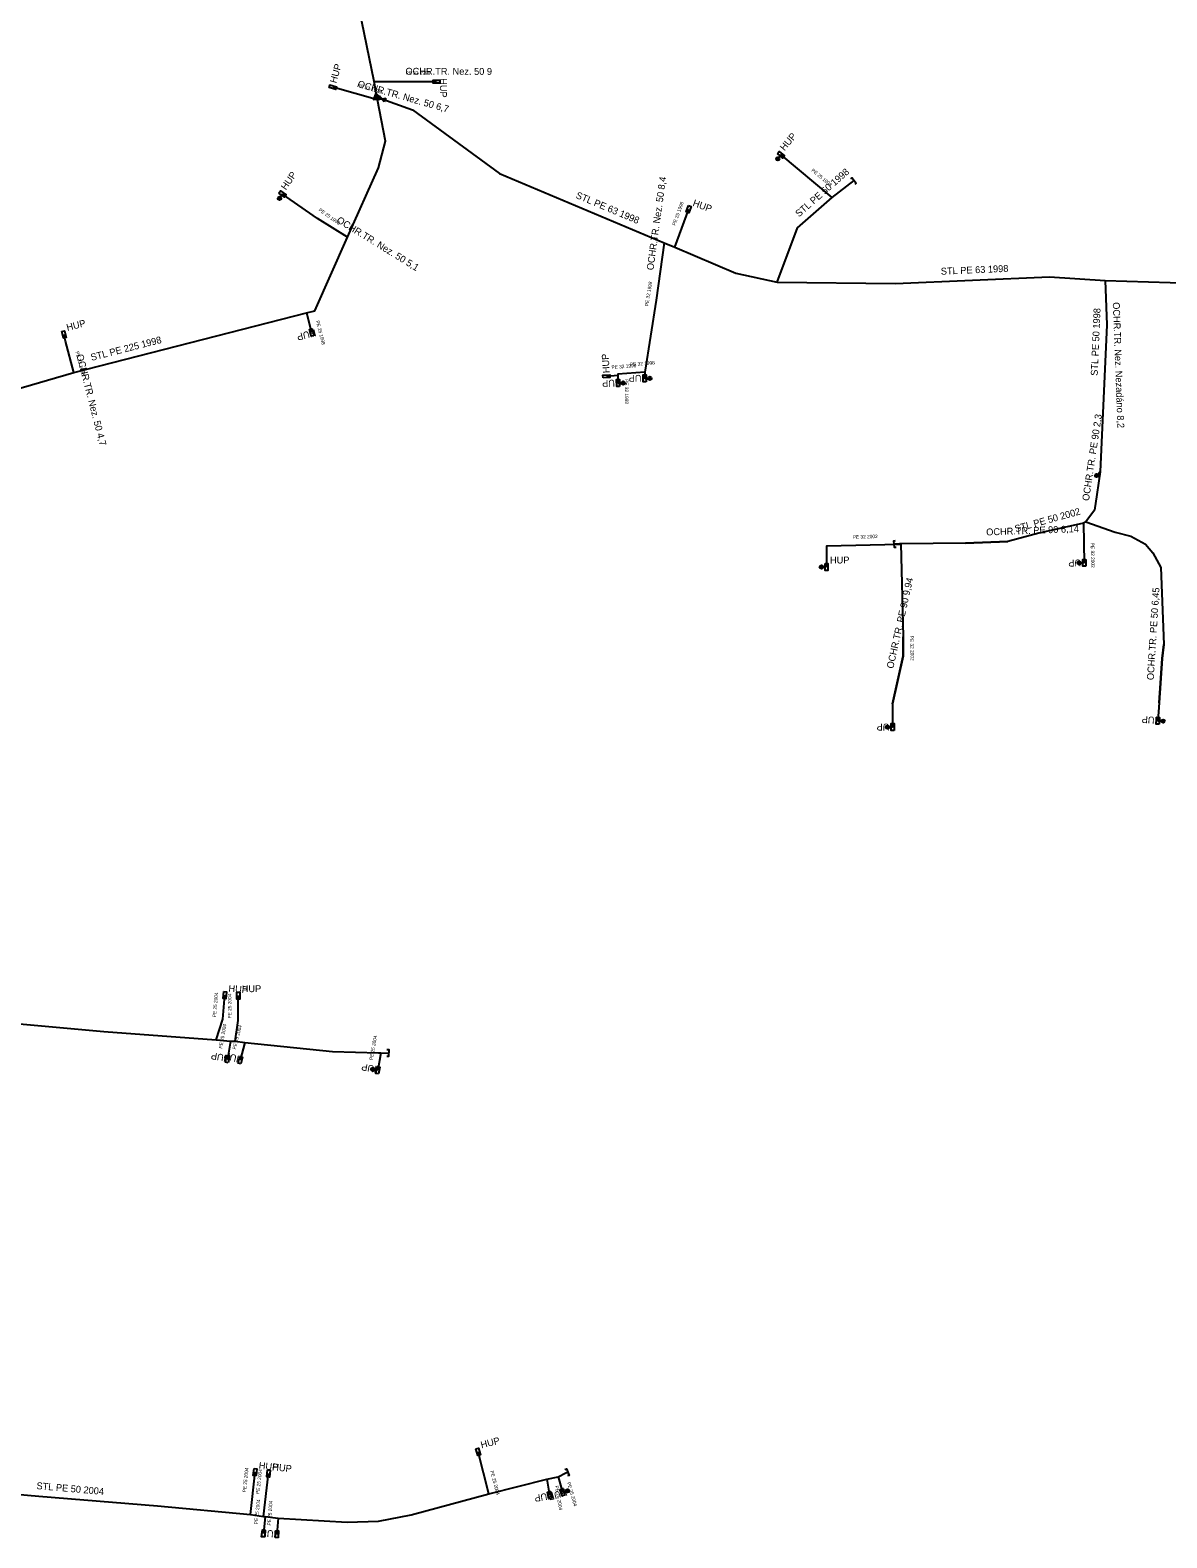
# Model space of a CAD drawing. Extents: x -741240 to -740302, y -1028024 to -1027535.
# Drawn here: x -740829.5 to -740664.5, y -1027972.7 to -1027754 of the extents above; entities that cross this region are included whole.
import ezdxf

# ---------------------------------------------------------------- set-up
doc = ezdxf.new("R2010")
doc.units = 0
for name, color, linetype in [('ST OP Chráni_ka - provoz', 7, 'Continuous'), ('ST Úsek p_ípojky - provoz', 7, 'Continuous'), ('ST Úsek plynovodu - provoz', 7, 'Continuous'), ('ST_HUP_22_23_popis', 7, 'Continuous'), ('Vrstva 1', 7, 'Continuous')]:
    doc.layers.add(name, color=color, linetype=linetype)

msp = doc.modelspace()

# ---------------------------------------------------------------- linework, layer by layer
at = {"layer": 'ST OP Chráni_ka - provoz'}
for points in [[(-740779.07, -1027764.12), (-740785.55, -1027762.27)], [(-740779.53, -1027761.46), (-740770.5, -1027761.48)], [(-740783.44, -1027784.02), (-740787.77, -1027781.35)], [(-740737.47, -1027784.86), (-740738.62, -1027793.18)], [(-740673.51, -1027790.31), (-740673.27, -1027796.74)], [(-740823.13, -1027803.69), (-740824.31, -1027799.11)], [(-740674.69, -1027821.36), (-740675.03, -1027823.64)], [(-740693.77, -1027828.43), (-740687.64, -1027828.21)], [(-740667.66, -1027828.57), (-740666.6, -1027829.81)], [(-740702.79, -1027844.79), (-740702.79, -1027842)], [(-740665.25, -1027845.16), (-740664.97, -1027843.11)], [(-740704.33, -1027851.74), (-740702.79, -1027844.79)], [(-740665.65, -1027851.6), (-740665.25, -1027845.16)]]:
    msp.add_lwpolyline(points, dxfattribs=at)
at = {"layer": 'ST Úsek p_ípojky - provoz'}
for points in [[(-740779.07, -1027764.12), (-740785.55, -1027762.27)], [(-740779.53, -1027761.46), (-740770.5, -1027761.48)], [(-740713.09, -1027778.29), (-740720.52, -1027772.09)], [(-740783.44, -1027784.02), (-740787.77, -1027781.35), (-740792.85, -1027777.79)], [(-740735.94, -1027785.5), (-740733.92, -1027779.98)], [(-740737.47, -1027784.86), (-740738.62, -1027793.18), (-740740.3, -1027803.6)], [(-740789.36, -1027795.01), (-740788.62, -1027797.89)], [(-740823.13, -1027803.69), (-740824.31, -1027799.11), (-740824.56, -1027798.14)], [(-740740.3, -1027803.6), (-740744.18, -1027803.9), (-740744.18, -1027804.1)], [(-740740.3, -1027803.6), (-740740.3, -1027804.52)], [(-740744.18, -1027804.1), (-740745.86, -1027804.23)], [(-740744.18, -1027804.1), (-740744.17, -1027805.2)], [(-740676.65, -1027825.55), (-740676.53, -1027831.28)], [(-740676.3, -1027825.35), (-740672.06, -1027826.85), (-740669.79, -1027827.41), (-740667.66, -1027828.57), (-740666.6, -1027829.81), (-740665.44, -1027831.95), (-740664.97, -1027843.11), (-740665.25, -1027845.17), (-740665.65, -1027851.6), (-740665.84, -1027854.19)], [(-740703.32, -1027828.52), (-740703.31, -1027828.62), (-740713.93, -1027828.87), (-740713.92, -1027831.88)], [(-740703.13, -1027828.51), (-740702.8, -1027841.97), (-740702.81, -1027844.83), (-740704.33, -1027851.74), (-740704.33, -1027855.11)], [(-740802.46, -1027900.48), (-740801.52, -1027897.49), (-740801.22, -1027893.99)], [(-740799.71, -1027900.69), (-740799.27, -1027897.65), (-740799.26, -1027894.06)], [(-740800.38, -1027900.65), (-740800.85, -1027903.27)], [(-740798.33, -1027900.86), (-740798.98, -1027903.45)], [(-740778.56, -1027902.38), (-740779.02, -1027904.89)], [(-740762.89, -1027966.32), (-740764.46, -1027960.25)], [(-740797.51, -1027969.34), (-740796.83, -1027963.18)], [(-740795.59, -1027969.61), (-740794.87, -1027963.39)], [(-740754.51, -1027964.2), (-740754.1, -1027966.54)], [(-740752.85, -1027963.88), (-740752.21, -1027966.11)], [(-740795.35, -1027969.64), (-740795.62, -1027972.1)], [(-740793.47, -1027969.85), (-740793.65, -1027972.21)]]:
    msp.add_lwpolyline(points, dxfattribs=at)
at = {"layer": 'ST Úsek plynovodu - provoz'}
for points in [[(-740779.14, -1027763.73), (-740779.53, -1027761.46), (-740784.18, -1027738.81), (-740784.78, -1027735.73), (-740787.5, -1027713.55), (-740785.95, -1027705.54), (-740785.73, -1027704.03), (-740784.6, -1027699.85), (-740781.84, -1027696.05), (-740745.38, -1027645.94), (-740739.82, -1027638.08), (-740732.42, -1027627.01), (-740726.2, -1027616.11), (-740721.12, -1027606.85), (-740712.18, -1027587.27), (-740708.46, -1027578.09), (-740696.29, -1027544.18), (-740693.16, -1027535.44)], [(-740883.81, -1027822.11), (-740883.44, -1027821.98), (-740849.9, -1027811.48), (-740831.91, -1027806.24), (-740823.13, -1027803.69), (-740789.36, -1027795.01), (-740788.17, -1027794.71), (-740783.44, -1027784.02), (-740778.93, -1027773.97), (-740777.89, -1027770.09), (-740779.07, -1027764.12), (-740779.14, -1027763.73)], [(-740779.14, -1027763.73), (-740779.01, -1027763.78)], [(-740779.01, -1027763.78), (-740778.45, -1027763.98)], [(-740778.45, -1027763.98), (-740773.98, -1027765.58), (-740761.36, -1027774.79), (-740737.47, -1027784.86), (-740735.94, -1027785.5), (-740727.07, -1027789.24), (-740721.07, -1027790.55)], [(-740721.07, -1027790.55), (-740718.11, -1027782.69), (-740713.09, -1027778.29), (-740709.91, -1027775.83)], [(-740721.07, -1027790.55), (-740703.89, -1027790.78), (-740681.58, -1027789.8), (-740673.51, -1027790.31)], [(-740673.51, -1027790.31), (-740673.27, -1027796.74), (-740674.2, -1027818.1)], [(-740673.51, -1027790.31), (-740657.76, -1027790.8), (-740634.73, -1027790.54), (-740621.24, -1027790.21), (-740613.68, -1027790.09), (-740601.67, -1027789.58), (-740582.6, -1027791.09), (-740550.15, -1027794.34), (-740534.5, -1027797.08), (-740521.37, -1027798.02)], [(-740674.2, -1027818.1), (-740674.69, -1027821.36), (-740675.03, -1027823.64), (-740676.3, -1027825.35), (-740676.65, -1027825.55), (-740683.12, -1027826.97), (-740687.64, -1027828.21), (-740693.77, -1027828.44), (-740703.13, -1027828.51), (-740703.32, -1027828.52), (-740704.11, -1027828.57)], [(-740903.99, -1027891.41), (-740901.7, -1027891.99), (-740895.06, -1027892.75), (-740880.28, -1027893.83), (-740878.36, -1027893.92), (-740862.24, -1027895.33), (-740850.48, -1027896.44), (-740839.91, -1027897.34), (-740838.48, -1027897.47), (-740818.75, -1027899.28), (-740802.46, -1027900.48), (-740800.38, -1027900.65), (-740799.71, -1027900.69), (-740798.33, -1027900.86), (-740785.58, -1027902.19), (-740778.94, -1027902.34), (-740778.56, -1027902.38), (-740777.45, -1027902.39)], [(-740906.69, -1027960.06), (-740899.91, -1027960.49), (-740889.42, -1027961.35), (-740887.34, -1027961.58), (-740875.19, -1027962.71), (-740859.41, -1027963.99), (-740847.3, -1027965.17), (-740845.48, -1027965.29), (-740843.37, -1027965.46), (-740841.36, -1027965.52), (-740828.21, -1027966.67), (-740810.98, -1027968.1), (-740797.51, -1027969.34), (-740795.59, -1027969.61), (-740795.35, -1027969.64), (-740793.47, -1027969.85), (-740783.45, -1027970.45), (-740778.94, -1027970.29), (-740774.16, -1027969.4), (-740762.89, -1027966.32), (-740754.51, -1027964.2), (-740752.85, -1027963.88), (-740751.75, -1027963.31), (-740751.46, -1027963.2)]]:
    msp.add_lwpolyline(points, dxfattribs=at)
at = {"layer": 'Vrstva 1'}
for p, q in [((-740778.82, -1027763.53), (-740779.02, -1027764.09)), ((-740779.02, -1027764.09), (-740777.88, -1027763.87)), ((-740778.08, -1027764.43), (-740778.82, -1027763.53)), ((-740777.88, -1027763.87), (-740778.08, -1027764.43)), ((-740720.52, -1027772.09), (-740720.84, -1027772.48)), ((-740792.85, -1027777.79), (-740793.14, -1027778.2)), ((-740744.17, -1027805.2), (-740743.67, -1027805.2)), ((-740740.3, -1027804.52), (-740739.8, -1027804.52)), ((-740674.2, -1027818.1), (-740674.56, -1027818.45)), ((-740713.92, -1027831.88), (-740714.42, -1027831.88)), ((-740676.53, -1027831.28), (-740677.03, -1027831.29)), ((-740665.84, -1027854.19), (-740665.34, -1027854.23)), ((-740704.33, -1027855.11), (-740704.84, -1027855.11)), ((-740779.02, -1027904.89), (-740779.51, -1027904.8)), ((-740752.21, -1027966.11), (-740751.72, -1027965.98))]:
    msp.add_line(p, q, dxfattribs=at)
for points in [[(-740786.09, -1027762.32), (-740785.98, -1027761.94), (-740785.01, -1027762.21), (-740785.12, -1027762.6)], [(-740770, -1027761.28), (-740770, -1027761.68), (-740771, -1027761.68), (-740771, -1027761.28)], [(-740779.31, -1027763.14), (-740779.65, -1027764.08), (-740778.54, -1027763.95)], [(-740779.5, -1027763.96), (-740778.75, -1027763.87), (-740779.27, -1027763.33)], [(-740778.96, -1027763.8), (-740779.23, -1027763.51), (-740779.35, -1027763.84)], [(-740721.03, -1027771.92), (-740720.77, -1027771.62), (-740720.01, -1027772.26), (-740720.26, -1027772.56)], [(-740793.37, -1027777.67), (-740793.14, -1027777.34), (-740792.33, -1027777.91), (-740792.56, -1027778.24)], [(-740733.94, -1027779.44), (-740733.56, -1027779.58), (-740733.9, -1027780.52), (-740734.28, -1027780.38)], [(-740788.3, -1027798.33), (-740788.69, -1027798.42), (-740788.93, -1027797.45), (-740788.55, -1027797.36)], [(-740824.88, -1027797.7), (-740824.49, -1027797.61), (-740824.24, -1027798.58), (-740824.63, -1027798.67)], [(-740746.34, -1027804.46), (-740746.37, -1027804.07), (-740745.38, -1027804), (-740745.35, -1027804.39)], [(-740740.1, -1027805.02), (-740740.5, -1027805.02), (-740740.5, -1027804.02), (-740740.1, -1027804.02)], [(-740743.96, -1027805.7), (-740744.36, -1027805.7), (-740744.38, -1027804.7), (-740743.98, -1027804.7)], [(-740714.12, -1027831.38), (-740713.72, -1027831.38), (-740713.71, -1027832.38), (-740714.11, -1027832.38)], [(-740676.32, -1027831.78), (-740676.72, -1027831.78), (-740676.74, -1027830.78), (-740676.34, -1027830.78)], [(-740665.68, -1027854.7), (-740666.08, -1027854.67), (-740666.01, -1027853.68), (-740665.61, -1027853.7)], [(-740704.13, -1027855.61), (-740704.53, -1027855.61), (-740704.53, -1027854.61), (-740704.13, -1027854.61)], [(-740801.37, -1027893.48), (-740800.97, -1027893.51), (-740801.06, -1027894.51), (-740801.46, -1027894.47)], [(-740799.46, -1027893.56), (-740799.06, -1027893.56), (-740799.06, -1027894.56), (-740799.46, -1027894.56)], [(-740800.74, -1027903.8), (-740801.13, -1027903.73), (-740800.96, -1027902.74), (-740800.56, -1027902.81)], [(-740798.91, -1027903.98), (-740799.3, -1027903.88), (-740799.05, -1027902.91), (-740798.67, -1027903.01)], [(-740778.91, -1027905.42), (-740779.3, -1027905.35), (-740779.13, -1027904.36), (-740778.73, -1027904.43)], [(-740764.78, -1027959.81), (-740764.39, -1027959.71), (-740764.14, -1027960.68), (-740764.53, -1027960.78)], [(-740796.97, -1027962.66), (-740796.57, -1027962.71), (-740796.68, -1027963.7), (-740797.08, -1027963.66)], [(-740795.01, -1027962.87), (-740794.62, -1027962.91), (-740794.73, -1027963.91), (-740795.13, -1027963.86)], [(-740751.88, -1027966.54), (-740752.26, -1027966.65), (-740752.54, -1027965.69), (-740752.15, -1027965.58)], [(-740753.82, -1027966.99), (-740754.21, -1027967.06), (-740754.38, -1027966.08), (-740753.99, -1027966.01)], [(-740795.48, -1027972.62), (-740795.88, -1027972.58), (-740795.77, -1027971.58), (-740795.37, -1027971.63)], [(-740793.49, -1027972.72), (-740793.88, -1027972.69), (-740793.81, -1027971.7), (-740793.42, -1027971.72)]]:
    msp.add_lwpolyline(points, close=True, dxfattribs=at)
for points in [[(-740710.41, -1027775.59), (-740710.22, -1027775.44), (-740709.6, -1027776.22), (-740709.8, -1027776.38)], [(-740703.83, -1027829.05), (-740704.08, -1027829.07), (-740704.15, -1027828.07), (-740703.9, -1027828.05)], [(-740777.69, -1027901.89), (-740777.44, -1027901.89), (-740777.46, -1027902.89), (-740777.71, -1027902.89)], [(-740751.88, -1027962.83), (-740751.65, -1027962.73), (-740751.27, -1027963.66), (-740751.5, -1027963.75)]]:
    msp.add_lwpolyline(points, dxfattribs=at)
for centre, radius in [((-740721, -1027772.67), 0.249), ((-740721.07, -1027772.59), 0.0614), ((-740720.91, -1027772.73), 0.0614), ((-740793.28, -1027778.41), 0.249), ((-740793.36, -1027778.34), 0.0614), ((-740793.19, -1027778.46), 0.0614), ((-740743.42, -1027805.2), 0.249), ((-740743.43, -1027805.09), 0.0614), ((-740743.43, -1027805.3), 0.0614), ((-740739.55, -1027804.52), 0.249), ((-740739.56, -1027804.41), 0.0614), ((-740739.56, -1027804.62), 0.0614), ((-740674.73, -1027818.63), 0.249), ((-740674.79, -1027818.55), 0.0614), ((-740674.65, -1027818.7), 0.0614), ((-740714.67, -1027831.88), 0.249), ((-740714.66, -1027831.78), 0.0614), ((-740714.66, -1027831.98), 0.0614), ((-740677.28, -1027831.3), 0.249), ((-740677.27, -1027831.2), 0.0614), ((-740677.27, -1027831.4), 0.0614), ((-740665.09, -1027854.24), 0.249), ((-740665.11, -1027854.34), 0.0614), ((-740665.1, -1027854.13), 0.0614), ((-740705.09, -1027855.12), 0.249), ((-740705.07, -1027855.02), 0.0614), ((-740705.07, -1027855.22), 0.0614), ((-740779.76, -1027904.76), 0.249), ((-740779.73, -1027904.66), 0.0614), ((-740779.76, -1027904.87), 0.0614), ((-740751.48, -1027965.91), 0.249), ((-740751.53, -1027965.81), 0.0614), ((-740751.47, -1027966.01), 0.0614)]:
    msp.add_circle(centre, radius, dxfattribs=at)

# ---------------------------------------------------------------- texts
at = {"layer": 'ST OP Chráni_ka - provoz'}
for s, rotation, p in [('OCHR.TR. Nez. 50 9', 359.8731, (-740775.01, -1027760.47)), ('OCHR.TR. Nez. 50 6,7', 344.0663, (-740782.03, -1027762.23)), ('OCHR.TR. Nez. 50 8,4', 82.1381, (-740739.04, -1027788.88)), ('OCHR.TR. Nez. 50 5,1', 328.3408, (-740785.08, -1027781.83)), ('OCHR.TR. Nez. Nezadáno 8,2', 272.1376, (-740672.39, -1027793.49)), ('OCHR.TR. Nez. 50 4,7', 284.4476, (-740822.75, -1027801.15)), ('OCHR.TR. PE 90 2,3', 81.4754, (-740675.85, -1027822.35)), ('OCHR.TR. PE 90 6,14', 2.1083, (-740690.74, -1027827.32)), ('OCHR.TR. PE 90 9,94', 77.5506, (-740704.24, -1027846.69)), ('OCHR.TR. PE 50 6,45', 86.4192, (-740666.45, -1027848.32))]:
    msp.add_text(s, height=1, rotation=rotation, dxfattribs=at).set_placement(p)
at = {"layer": 'ST Úsek p_ípojky - provoz'}
for s, rotation, p in [('PE 32 1998', 359.8795, (-740775.01, -1027760.47)), ('PE 32 1998', 344.0581, (-740782.04, -1027762.23)), ('PE 25 1998', 320.1527, (-740716.16, -1027774.42)), ('PE 25 1998', 324.9701, (-740787.65, -1027780.21)), ('PE 25 1998', 69.8912, (-740735.87, -1027782.4)), ('PE 32 1998', 80.8411, (-740739.78, -1027794.08)), ('PE 25 1998', 284.4336, (-740788.02, -1027796.2)), ('PE 32 1998', 284.4476, (-740822.88, -1027800.67)), ('PE 32 1998', 4.4248, (-740745.1, -1027803.17)), ('PE 32 1998', 4.4213, (-740742.42, -1027802.76)), ('PE 32 1998', 270.5213, (-740743.18, -1027804.64)), ('PE 32 2002', 1.3436, (-740710.1, -1027827.78)), ('PE 32 2002', 271.1787, (-740675.59, -1027828.39)), ('PE 32 2002', 271.405, (-740701.8, -1027841.87)), ('PE 25 2004', 85.0777, (-740802.5, -1027897.22)), ('PE 25 2004', 89.8402, (-740800.27, -1027897.39)), ('PE 25 2004', 79.9086, (-740801.6, -1027901.78)), ('PE 25 2004', 75.8232, (-740799.63, -1027901.91)), ('PE 25 2004', 79.6229, (-740779.77, -1027903.45)), ('PE 25 2004', 83.7098, (-740798.16, -1027966.15)), ('PE 25 2004', 83.4223, (-740796.22, -1027966.38)), ('PE 25 2004', 284.4769, (-740762.71, -1027963.04)), ('PE 25 2004', 279.8668, (-740753.32, -1027965.19)), ('PE 25 2004', 286.1418, (-740751.57, -1027964.72)), ('PE 25 2004', 83.6598, (-740796.48, -1027970.76)), ('PE 25 2004', 85.709, (-740794.56, -1027970.95))]:
    msp.add_text(s, height=0.5, rotation=rotation, dxfattribs=at).set_placement(p)
at = {"layer": 'ST Úsek plynovodu - provoz'}
for s, rotation, p in [('STL PE 50 1998', 41.2344, (-740717.91, -1027781.18)), ('STL PE 63 1998', 337.1438, (-740750.38, -1027778.33)), ('STL PE 63 1998', 2.5152, (-740697.32, -1027789.49)), ('STL PE 50 1998', 87.5068, (-740674.59, -1027804.16)), ('STL PE 225 1998', 14.4149, (-740820.54, -1027801.99)), ('STL PE 50 2002', 15.3582, (-740686.47, -1027826.85)), ('STL PE 50 2004', 354.9895, (-740828.57, -1027965.64))]:
    msp.add_text(s, height=1, rotation=rotation, dxfattribs=at).set_placement(p)
at = {"layer": 'ST_HUP_22_23_popis'}
for rotation, p in [(74, (-740785.05, -1027761.77)), (270, (-740770, -1027760.98)), (50, (-740720.02, -1027771.59)), (55, (-740792.35, -1027777.29)), (340, (-740733.42, -1027779.48)), (14, (-740824.06, -1027797.64)), (194, (-740788.12, -1027797.39)), (94, (-740745.36, -1027803.73)), (180, (-740739.8, -1027804.02)), (181, (-740743.67, -1027804.7)), (0.23, (-740713.42, -1027831.38)), (181, (-740676.03, -1027830.78)), (176, (-740665.34, -1027853.69)), (180, (-740703.83, -1027854.61)), (355, (-740800.72, -1027893.49)), (170, (-740800.35, -1027902.77)), (165.82, (-740798.48, -1027902.95)), (170, (-740778.52, -1027904.39)), (14.48, (-740763.96, -1027959.75)), (353.71, (-740796.33, -1027962.68)), (353.42, (-740794.37, -1027962.89)), (196, (-740751.71, -1027965.61)), (190, (-740753.6, -1027966.04)), (176, (-740793.15, -1027971.71))]:
    msp.add_text('HUP', height=1, rotation=rotation, dxfattribs=at).set_placement(p)
msp.add_text('HUP', height=1, dxfattribs=at).set_placement((-740798.76, -1027893.56))

doc.saveas('drawing.dxf')
